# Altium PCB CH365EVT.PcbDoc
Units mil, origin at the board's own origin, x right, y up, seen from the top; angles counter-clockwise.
Board outline 3165 x 3014.02 mil, 2 copper layers (TopLayer, BottomLayer); 26 components, 99 nets, 425 pads, 157 vias.
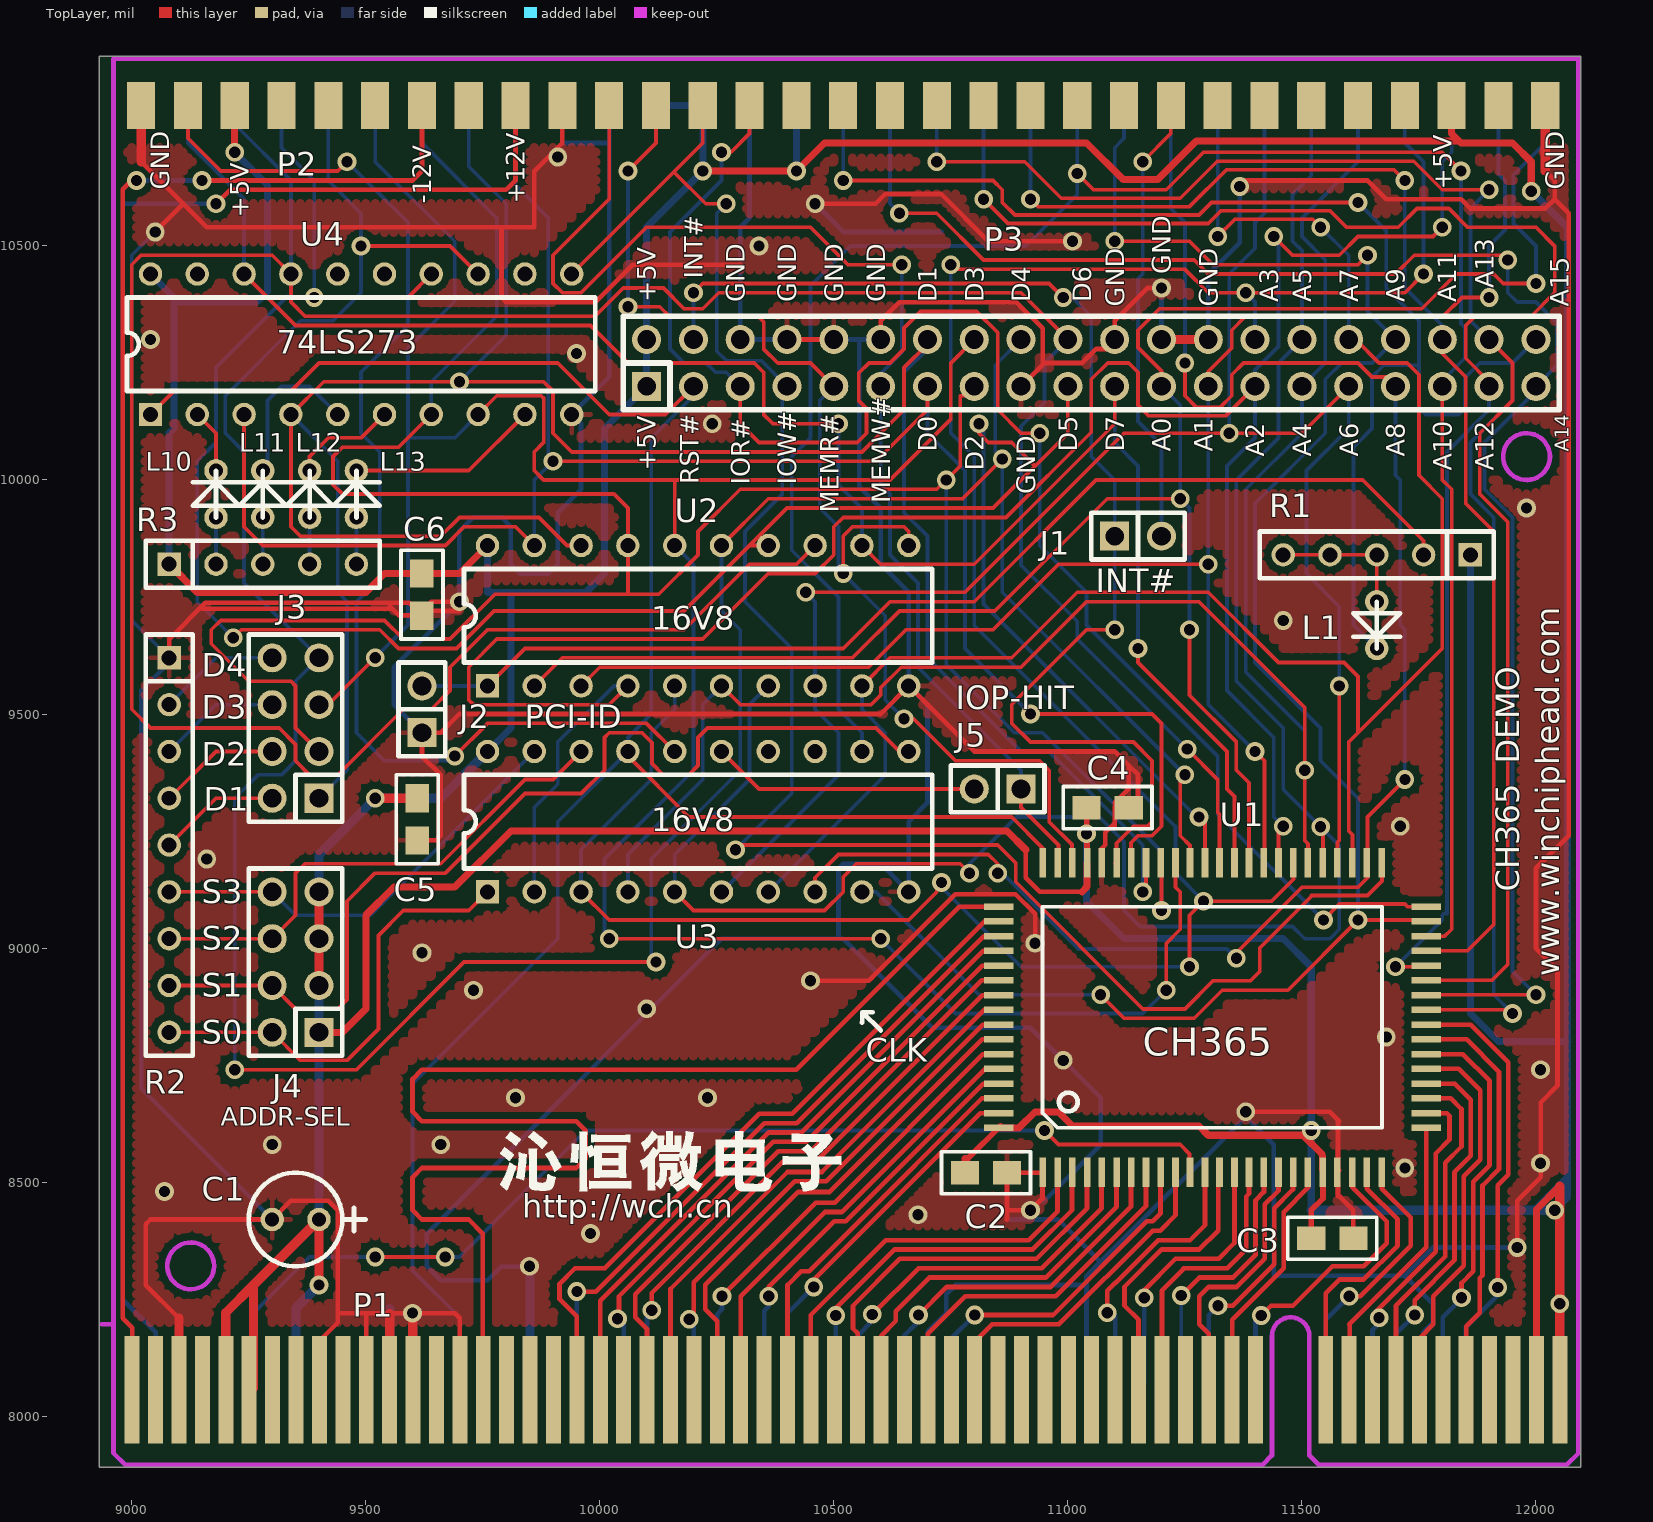
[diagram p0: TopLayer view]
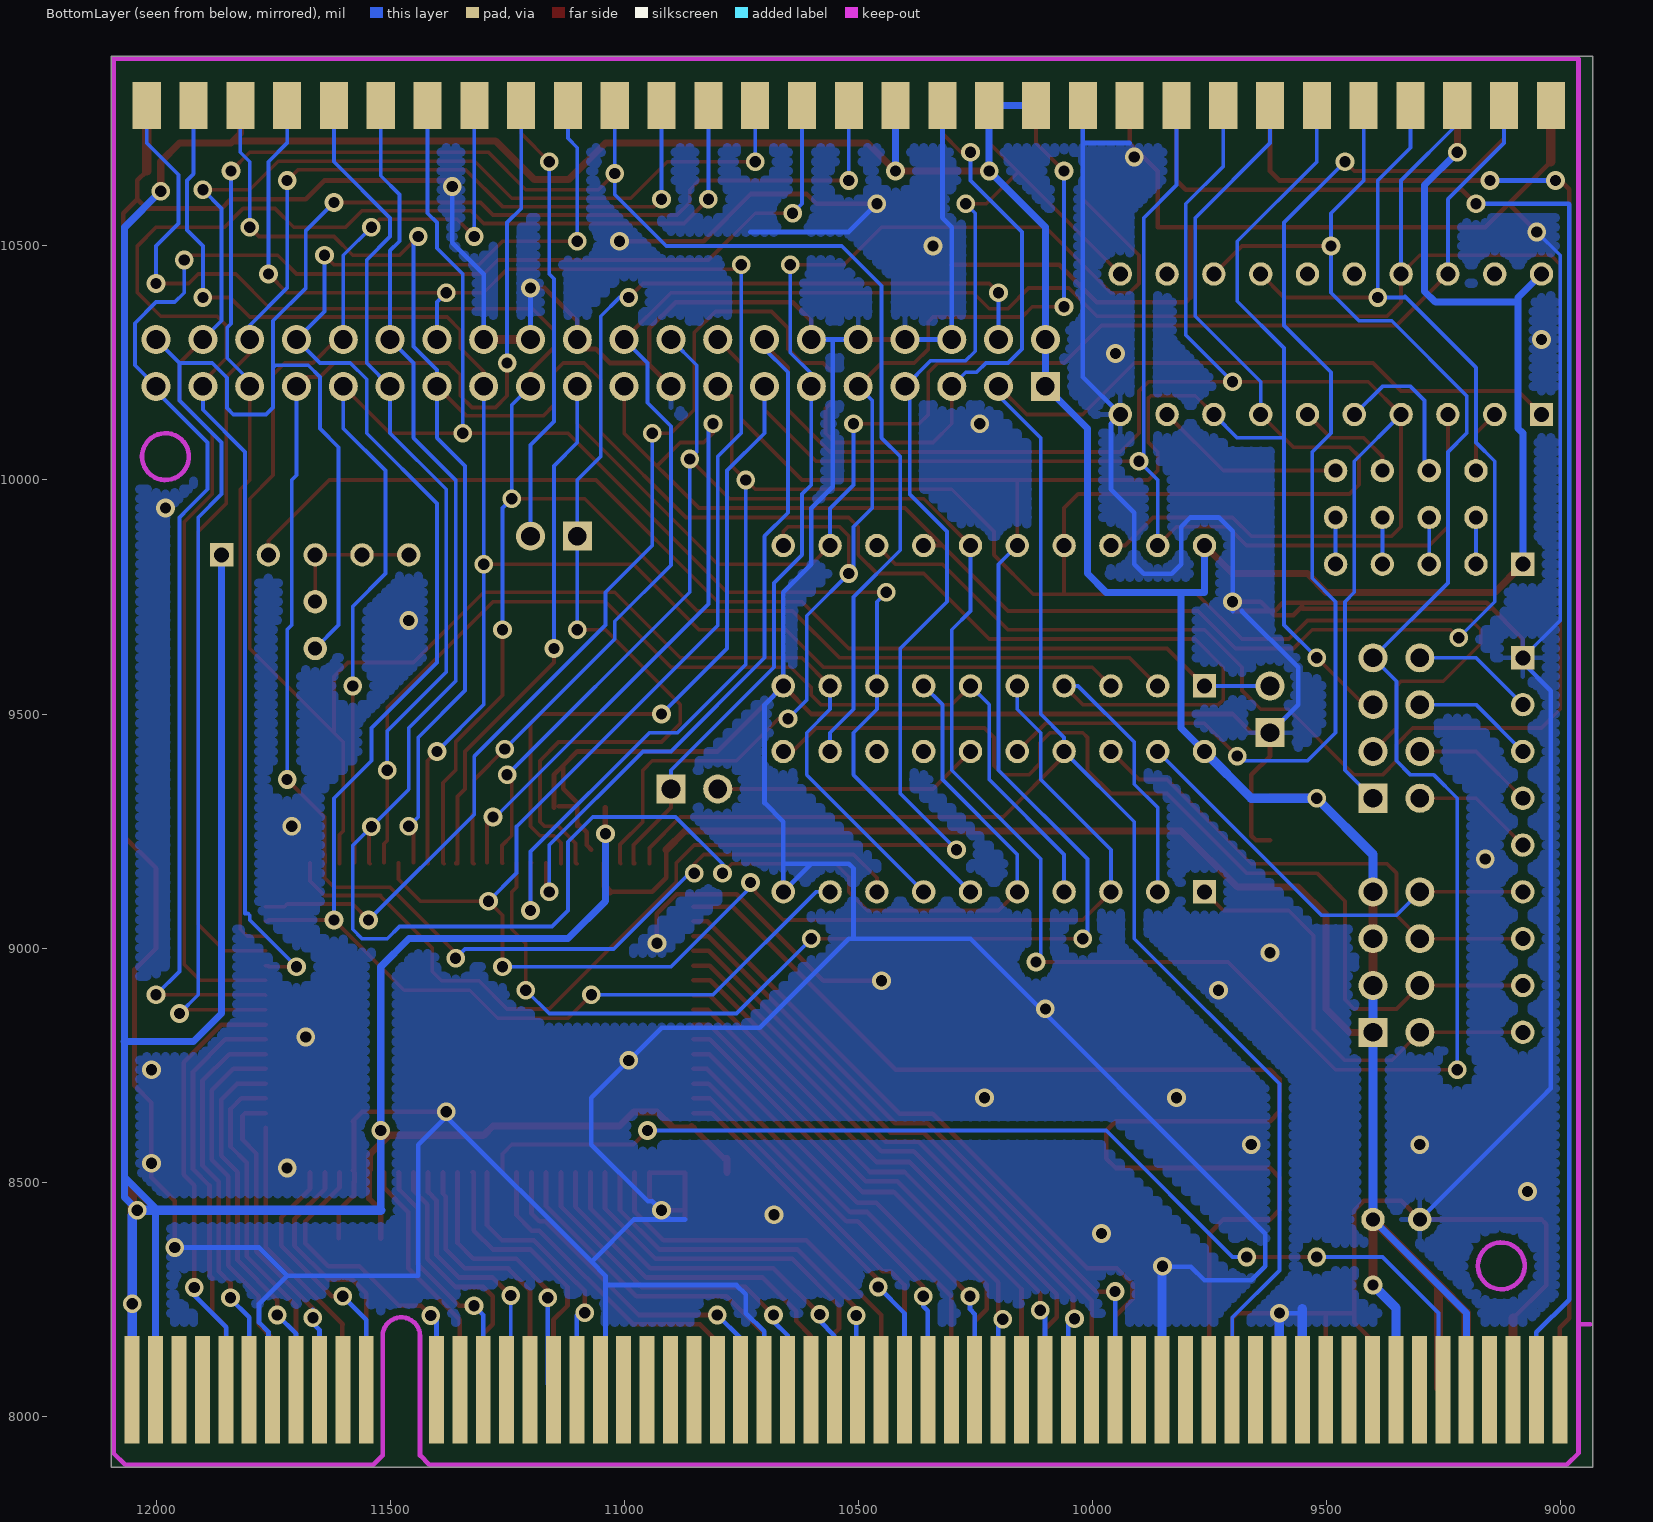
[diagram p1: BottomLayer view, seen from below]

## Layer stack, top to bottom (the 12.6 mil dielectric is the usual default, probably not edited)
TopSolder: solder mask 0.4, Solder Resist, Dk 3.5
TopLayer: signal copper 1.4
Dielectric1: core 12.6, FR-4, Dk 4.8
BottomLayer: signal copper 1.4
BottomSolder: solder mask 0.4, Solder Resist, Dk 3.5

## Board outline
8930.98,7890.98 12095.98,7890.98 12095.98,10905 8930.98,10905

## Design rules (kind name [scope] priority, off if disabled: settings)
Clearance Clearance_1 [(InPoly)] p1: gap=15 ignorepadtopadclearanceinfootprint=FALSE
Clearance [All] p2: gap=10 ignorepadtopadclearanceinfootprint=FALSE
FabricationTestPointUsage TestPointUsage [All] p1: valid=0 allowmultiple=FALSE
FabricationTestpoint Testpoint [All] p1: side=3 testpointundercomponent=TRUE minsize=40 maxsize=100 preferedsize=60 minholesize=20 maxholesize=40 preferedholesize=32 testpointgrid=1 allowsidetop=TRUE allowsidebottom=TRUE usegrid=TRUE gridtolerance=0.01
PasteMaskExpansion PasteMaskExpansion_1 [All] p1: expansion=0
PasteMaskExpansion [All] p2: expansion=0
PlaneClearance PlaneClearance_1 [All] p1: clearance=20
PlaneClearance [All] p2: clearance=10
PlaneConnect PlaneConnect_1 [All] p1: planeconnectstyle=Relief reliefexpansion=20 reliefentries=4 reliefconductorwidth=10 reliefairgap=10
PlaneConnect [All] p2: planeconnectstyle=Relief reliefexpansion=20 reliefentries=4 reliefconductorwidth=10 reliefairgap=10
PolygonConnect [All] p1: connectstyle=Relief reliefconductorwidth=10 reliefentries=4 polygonreliefangle="90 Angle" airgapwidth=10
RoutingPriority RoutingPriority_1 [InNet('+12')] p1: routingpriority=9
RoutingPriority RoutingPriority_2 [InNet('-12')] p2: routingpriority=8
RoutingPriority RoutingPriority_3 [InNet('VCC')] p3: routingpriority=5
RoutingPriority [All] p4: routingpriority=0
RoutingVias [All] p1: holewidth=24 width=40 viastyle="Through Hole" minholewidth=20 minwidth=30 maxholewidth=24 maxwidth=40
ShortCircuit ShortCircuit_1 [All] p1: allowed=FALSE
ShortCircuit [All] p2: allowed=FALSE
SolderMaskExpansion SolderMaskExpansion_1 [All] p1: expansion=8 istentingtop=FALSE
UnRoutedNet UnRoutedNet_1 [All] p1:
UnRoutedNet [All] p2:
Width Width_3 [InNet('VCC')] p1: maxlimit=20 minlimit=8 preferedwidth=15
Width Width_4 [InNet('GND')] p2: maxlimit=20 minlimit=8 preferedwidth=10
Width Width_1 [InNet('-12')] p3: maxlimit=20 minlimit=8 preferedwidth=10
Width Width_2 [InNet('+12')] p4: maxlimit=20 minlimit=8 preferedwidth=10
Width "Width Board" [All] p5: maxlimit=20 minlimit=8 preferedwidth=8
22 further rules are at their usual default settings.

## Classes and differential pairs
component class CH365EVT: C1 C2 C3 C4 C5 C6 J1 J2 J3 J4 J5 L1 P1 P2 R1 R2 U1 U2 U3
net class "Power Class": +12 -12 GND VCC

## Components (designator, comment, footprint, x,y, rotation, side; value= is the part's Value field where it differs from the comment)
C1 "100uF" CD0.1 9400,8420 r0 top
C2 "0.1uF" RC1 10780,8520 r0 top
C3 "0.1uF" RC1 11520,8380 r0 top
C4 "0.1uF" RC1 11040,9300 r0 top
C5 "0.1uF" RC1 9610,9320 r270 top
C6 "0.1uF" RC1 9620,9800 r270 top
J1 "" SIP2 11100,9880 r0 top
J2 "" SIP2 9620,9460 r90 top
J3 "4PIN" IDC8 9400,9320 r90 top
J4 "4PIN" IDC8 9400,8820 r90 top
J5 "" SIP2 10900,9340 r180 top
L1 "" DIODE0.1 11660,9740 r270 top
L10 "" DIODE0.1 9180,9920 r90 top
L11 "" DIODE0.1 9280,9920 r90 top
L12 "" DIODE0.1 9380,9920 r90 top
L13 "" DIODE0.1 9480,9920 r90 top
P1 "PCI" PCI32 9000.98,8045.98 r0 top
P2 "ISA" PC_BUS 8200,14400 r0 top
P3 "40PIN" IDC40 10100,10200 r0 top
R1 "4K7" SIP5 11860,9840 r180 top
R2 "4K7" SIP9 9080,9620 r270 top
R3 "4K7" SIP5 9080,9820 r0 top
U1 "CH365" PQFP80 11000.98,8670.98 r0 top
U2 "16V8" DIP20 9760,9560 r90 top
U3 "16V8" DIP20 9760,9120 r90 top
U4 "74LS273" DIP20 9040,10140 r90 top

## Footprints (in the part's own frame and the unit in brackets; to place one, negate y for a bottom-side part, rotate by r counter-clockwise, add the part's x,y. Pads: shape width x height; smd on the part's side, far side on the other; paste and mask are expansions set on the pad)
CD0.1 [mil]
  round 50 hole 30: 1(0,0) 2(-100,0)
  silkscreen extent -150,-100 100,100
DIODE0.1 [mil]
  round 50 hole 30: A(0,0) K(100,0)
  silkscreen extent 0,-50 100,50
DIP20 [mil]
  rect 50x50 hole 32: 1(0,0)
  round 50 hole 32: 2(0,-100) 3(0,-200) 4(0,-300) 5(0,-400) 6(0,-500) 7(0,-600) 8(0,-700) 9(0,-800) 10(0,-900) 11(300,-900) 12(300,-800) 13(300,-700) 14(300,-600) 15(300,-500) 16(300,-400) 17(300,-300) 18(300,-200) 19(300,-100) 20(300,0)
  silkscreen extent 50,-950 250,50
IDC8 [mil]
  rect 62x62 hole 40: 1(0,0)
  round 62 hole 40: 2(0,100) 3(100,0) 4(100,100) 5(200,0) 6(200,100) 7(300,0) 8(300,100)
  silkscreen extent -50,-50 350,150
IDC40 [mil]
  rect 62x62 hole 40: 1(0,0)
  round 62 hole 40: 2(0,100) 3(100,0) 4(100,100) 5(200,0) 6(200,100) 7(300,0) 8(300,100) 9(400,0) 10(400,100) 11(500,0) 12(500,100) 13(600,0) 14(600,100) 15(700,0) 16(700,100) 17(800,0) 18(800,100) 19(900,0) 20(900,100) 21(1000,0) 22(1000,100) 23(1100,0) 24(1100,100) 25(1200,0) 26(1200,100) 27(1300,0) 28(1300,100) 29(1400,0) 30(1400,100) 31(1500,0) 32(1500,100) 33(1600,0) 34(1600,100) 35(1700,0) 36(1700,100) 37(1800,0) 38(1800,100) 39(1900,0) 40(1900,100)
  silkscreen extent -50,-50 1950,150
PC_BUS [mil]
  rect 60x100 smd: 1(820,-3600) 2(920,-3600) 3(1020,-3600) 4(1120,-3600) 5(1220,-3600) 6(1320,-3600) 7(1420,-3600) 8(1520,-3600) 9(1620,-3600) 10(1720,-3600) 11(1820,-3600) 12(1920,-3600) 13(2020,-3600) 14(2120,-3600) 15(2220,-3600) 16(2320,-3600) 17(2420,-3600) 18(2520,-3600) 19(2620,-3600) 20(2720,-3600) 21(2820,-3600) 22(2920,-3600) 23(3020,-3600) 24(3120,-3600) 25(3220,-3600) 26(3320,-3600) 27(3420,-3600) 28(3520,-3600) 29(3620,-3600) 30(3720,-3600) 31(3820,-3600)
  rect 60x100 smd far side: 32(3820,-3600) 33(3720,-3600) 34(3620,-3600) 35(3520,-3600) 36(3420,-3600) 37(3320,-3600) 38(3220,-3600) 39(3120,-3600) 40(3020,-3600) 41(2920,-3600) 42(2820,-3600) 43(2720,-3600) 44(2620,-3600) 45(2520,-3600) 46(2420,-3600) 47(2320,-3600) 48(2220,-3600) 49(2120,-3600) 50(2020,-3600) 51(1920,-3600) 52(1820,-3600) 53(1720,-3600) 54(1620,-3600) 55(1520,-3600) 56(1420,-3600) 57(1320,-3600) 58(1220,-3600) 59(1120,-3600) 60(1020,-3600) 61(920,-3600) 62(820,-3600)
PCI32 [mil]
  rect 32x230 smd: 1(0,10) 2(50,10) 3(100,10) 4(150,10) 5(200,10) 6(250,10) 7(300,10) 8(350,10) 9(400,10) 10(450,10) 11(500,10) 12(550,10) 13(600,10) 14(650,10) 15(700,10) 16(750,10) 17(800,10) 18(850,10) 19(900,10) 20(950,10) 21(1000,10) 22(1050,10) 23(1100,10) 24(1150,10) 25(1200,10) 26(1250,10) 27(1300,10) 28(1350,10) 29(1400,10) 30(1450,10) 31(1500,10) 32(1550,10) 33(1600,10) 34(1650,10) 35(1700,10) 36(1750,10) 37(1800,10) 38(1850,10) 39(1900,10) 40(1950,10) 41(2000,10) 42(2050,10) 43(2100,10) 44(2150,10) 45(2200,10) 46(2250,10) 47(2300,10) 48(2350,10) 49(2400,10) 52(2550,10) 53(2600,10) 54(2650,10) 55(2700,10) 56(2750,10) 57(2800,10) 58(2850,10) 59(2900,10) 60(2950,10) 61(3000,10) 62(3050,10)
  rect 32x230 smd far side: 63(3050,10) 64(3000,10) 65(2950,10) 66(2900,10) 67(2850,10) 68(2800,10) 69(2750,10) 70(2700,10) 71(2650,10) 72(2600,10) 73(2550,10) 76(2400,10) 77(2350,10) 78(2300,10) 79(2250,10) 80(2200,10) 81(2150,10) 82(2100,10) 83(2050,10) 84(2000,10) 85(1950,10) 86(1900,10) 87(1850,10) 88(1800,10) 89(1750,10) 90(1700,10) 91(1650,10) 92(1600,10) 93(1550,10) 94(1500,10) 95(1450,10) 96(1400,10) 97(1350,10) 98(1300,10) 99(1250,10) 100(1200,10) 101(1150,10) 102(1100,10) 103(1050,10) 104(1000,10) 105(950,10) 106(900,10) 107(850,10) 108(800,10) 109(750,10) 110(700,10) 111(650,10) 112(600,10) 113(550,10) 114(500,10) 115(450,10) 116(400,10) 117(350,10) 118(300,10) 119(250,10) 120(200,10) 121(150,10) 122(100,10) 123(50,10) 124(0,10)
  KeepOutLayer lines w10: -65,150 -40,150 -40,-125 -15,-150 2415,-150 2435,-130 2435,125 cw(c2475,125) 2515,125 2515,-130 2535,-150 3065,-150 3090,-125 3090,150
PQFP80 [mil]
  rect 14x63 smd: 1(-55,-150) 2(-23,-150) 3(8,-150) 4(40,-150) 5(71,-150) 6(103,-150) 7(134,-150) 8(166,-150) 9(197,-150) 10(229,-150) 11(260,-150) 12(292,-150) 13(323,-150) 14(355,-150) 15(386,-150) 16(418,-150) 17(449,-150) 18(481,-150) 19(512,-150) 20(544,-150) 21(575,-150) 22(607,-150) 23(638,-150) 24(670,-150) 41(670,511) 42(638,511) 43(607,511) 44(575,511) 45(544,511) 46(512,511) 47(481,511) 48(449,511) 49(418,511) 50(386,511) 51(355,511) 52(323,511) 53(292,511) 54(260,511) 55(229,511) 56(197,511) 57(166,511) 58(134,511) 59(103,511) 60(71,511) 61(40,511) 62(8,511) 63(-23,511) 64(-55,511)
  rect 63x14 smd: 25(765,-55) 26(765,-24) 27(765,8) 28(765,39) 29(765,71) 30(765,102) 31(765,134) 32(765,165) 33(765,197) 34(765,228) 35(765,260) 36(765,291) 37(765,323) 38(765,354) 39(765,386) 40(765,417) 65(-149,417) 66(-149,386) 67(-149,354) 68(-149,323) 69(-149,291) 70(-149,260) 71(-149,228) 72(-149,197) 73(-149,165) 74(-149,134) 75(-149,102) 76(-149,71) 77(-149,39) 78(-149,8) 79(-149,-24) 80(-149,-55)
  silkscreen extent -55,-55 670,417
RC1 [mil]
  rect 60x50 smd: 1(0,0) 2(90,0)
  silkscreen extent -50,-45 140,45
SIP2 [mil]
  rect 62x62 hole 40: 1(0,0)
  round 62 hole 40: 2(100,0)
  silkscreen extent -50,-50 150,50
SIP5 [mil]
  rect 50x50 hole 32: 1(0,0)
  round 50 hole 32: 2(100,0) 3(200,0) 4(300,0) 5(400,0)
  silkscreen extent -50,-50 450,50
SIP9 [mil]
  rect 50x50 hole 32: 1(0,0)
  round 50 hole 32: 2(100,0) 3(200,0) 4(300,0) 5(400,0) 6(500,0) 7(600,0) 8(700,0) 9(800,0)
  silkscreen extent -50,-50 850,50

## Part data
C1: library part Pro70E3.TMP_100u_5
C2 C3 C4 C5 C6: library part Pro70E3.TMP_0.1u_4
J1 J5: library part Pro70E3.TMP_UnNamed_6
J2: library part Pro70E3.TMP_UnNamed_1
J3 J4: library part Pro70E3.TMP_4PIN_7
L1 L10 L11 L12 L13: library part Pro70E3.TMP_UnNamed_3
P1: library part Pro70E3.TMP_PCI_9
P2: library part Pro70E3.TMP_ISA_13
R1 R3: library part Pro70E3.TMP_4K7_2
R2: library part Pro70E3.TMP_4K7_11
U1: library part Pro70E3.TMP_CH361_8
U2: library part Pro70E3.TMP_16V8_12
U3: library part Pro70E3.TMP_16V8_10

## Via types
v1: diameter 40, hole 24, TopLayer to BottomLayer, 157 vias

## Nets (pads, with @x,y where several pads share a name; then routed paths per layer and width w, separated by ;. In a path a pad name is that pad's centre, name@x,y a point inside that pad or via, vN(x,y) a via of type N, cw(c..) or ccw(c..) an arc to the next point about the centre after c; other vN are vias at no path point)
+12: P1.123 P2.9 | length 3582.2
  TopLayer w10: v1(9180,10590) 9210,10620 9800,10620 9820,10640 P2.9
  BottomLayer w10: P1.123 9050.98,8179.02 8980.98,8249.02 8980.98,10589.02 8981.96,10590 v1(9180,10590)
-12: P1.1 P2.7 | length 3368.5
  TopLayer w10: P1.1 9000.98,8189.02 8980.98,8209.02 8980.98,10620.98 9000,10640 v1(9010,10640) ; v1(9150,10640) 9600,10640 9620,10660 P2.7
  BottomLayer w10: v1(9010,10640) v1(9150,10640)
A0: P2.32 P3.23 U1.50 U2.2 | length 4120.7
  TopLayer w8: U2.2 9920,9620 10540,9620 10640,9720 10844,9720 11084,9960 v1(11240,9960) ; P3.23 11200,10233 11150,10283 11150,10320 11196,10366 11756,10366 11830,10440 11910,10440 11930,10420 v1(12000,10420) ; v1(11260,9680) 11260,9540 11360,9440 11360,9380 11386.98,9353.02 U1.50 U1.50@11385,9180
  BottomLayer w8: P3.23 11240,10160 v1(11240,9960) 11260,9940 v1(11260,9680) ; v1(12000,10420) 12000,10500 11952,10548 11952,10652 12020,10720 P2.32
A1: P2.33 P3.25 U1.49 U2.3 | length 3680
  TopLayer w8: U2.3 10000,9600 10574,9600 10654,9680 10840,9680 10980,9820 v1(11300,9820) ; P3.25 11300,10232 11350,10282 11350,10320 11378,10348 11800,10348 11842,10390 v1(11900,10390) ; v1(11400,9420) 11420,9400 11420,9180 11418.98,9180 U1.49
  BottomLayer w8: P3.25 11300,9520 v1(11400,9420) ; v1@11900,10380 11900,10500 11934,10534 11934,10640 11920,10654 P2.33
A2: P2.34 P3.27 U1.48 U2.4 U3.2 | length 5246.9
  TopLayer w8: U2.4 10020,9520 9730,9520 9720,9530 9720,9600 9780,9660 10220,9660 10360,9800 10460,9800 10500,9840 10500,9900 10520,9920 10868,9920 11050,10102 11050,10215 11085,10250 11130,10250 11150,10230 11150,10160 11173,10137 11337,10137 P3.27 ; v1(11440,10520) 11480,10480 11580,10480 11620,10520 11780,10520 v1(11800,10540) ; U1.48 11449.98,9249.98 v1(11460,9260)
  BottomLayer w8: U3.2 9860,9300 9910,9350 9910,9440 10030,9560 U2.4 ; v1(11440,10520) 11450,10510 11450,10285 11400,10235 11400,10090 11340,10030 11340,9550 11440,9450 11440,9280 v1(11460,9260) ; v1(11800,10540) 11800,10680 11820,10700 P2.34
A3: P2.35 P3.28 U1.47 U2.5 U3.3 | length 5486.9
  TopLayer w8: U3.3 10020,9060 10660,9060 10720,9120 v1@10720,9140 ; v1(10750,10460) 10760,10450 11250,10450 11300,10400 11720,10400 v1(11760,10440) ; v1(11260,8960) 11260,9070 v1(11290,9100) 11435,9100 11481.98,9146.98 U1.47
  BottomLayer w8: U3.3 9960,9210 10110,9360 10110,9460 10160,9510 U2.5 ; v1@10720,9140 10900,8960 v1(11260,8960) ; v1(10750,10460) 10750,10100 10800,10050 10800,9689 11230,9259 ; 11230,9260 11230,9160 v1(11290,9100) ; v1(11380,10400) 11400,10380 P3.28 ; P2.35 11720,10720 11760,10680 v1(11760,10440)
  other v1: 10730,9140
A4: P2.36 P3.29 U1.46 U2.6 U3.4 | length 3927.5
  TopLayer w8: U2.6 10300,9520 10580,9520 10600,9540 10600,9556 10644,9600 10900,9600 11040,9740 11280,9740 11506,9514 11506,9230 11512.98,9223.02 U1.46
  BottomLayer w8: U3.4 10060,9200 10220,9360 10220,9520 U2.6 ; v1(11506,9380) 11506,9464 11380,9590 11380,9980 11500,10100 P3.29 11550,10250 11550,10470 11500,10520 11500,10560 11620,10680 P2.36
A5: P2.37 P3.30 U1.45 U2.7 U3.5 | length 4307.2
  TopLayer w8: U3.5 10200,9080 10480,9080 10520,9120 10520,9152 10548,9180 10770,9180 v1(10790,9160) ; v1(11540,9259) 11544.98,9254.02 U1.45 U1.45@11543,9180
  BottomLayer w8: U3.5 10160,9200 10320,9360 10320,9520 U2.7 ; v1(10790,9160) 10790,9180 10890,9280 11067,9280 11120,9227 11120,9080 11154,9046 11480,9046 11506,9020 11560,9020 11580,9040 11580,9219 11460,9339 11460,9470 11360,9570 11360,10000 11450,10090 11450,10250 P3.30 11500,10490 11480,10510 11480,10610 11520,10650 P2.37
A6: P2.38 P3.31 U1.44 U2.8 U3.6 | length 3931.8
  TopLayer w8: v1(10440,9760) 10780,9760 11120,10100 11500,10100 P3.31 ; U1.44 11575.98,9225.98 11580,9230 v1(11580,9560)
  BottomLayer w8: U3.6 10510,9370 10510,9460 10460,9510 10460,9740 v1(10440,9760) ; v1(11345,10100) 11345,10440 11400,10495 11400,10550 11420,10570 P2.38 ; v1(11580,9560) 11580,9730 11510,9800 11510,10020 11600,10110 P3.31
A7: P2.39 P3.32 U1.43 U2.9 U3.7 | length 4021.8
  TopLayer w8: U2.9 10620,9620 10880,9620 11020,9760 11300,9760 11450,9610 11590,9610 11620,9580 11620,9460 ; v1(11320,10520) 11357,10557 11523,10557 v1(11540,10540) ; P3.32 11615,10300 11665,10250 11725,10250 11750,10225 11750,10010 11800,9960 11800,9640 11600,9440 11600,9250 11607.98,9242.02 U1.43@11607.98,9180
  BottomLayer w8: U3.7 10610,9370 10610,9460 10560,9510 U2.9 ; v1(11320,10520) P2.39 ; v1(11540,10540) 11600,10480 P3.32
A8: P2.40 P3.33 U1.42 U3.8 | length 3712.3
  TopLayer w8: U3.8 10460,9150 10510,9200 10830,9200 10850,9180 v1(10850,9160) ; v1(11250,10250) 11250,10180 11275,10155 11325,10155 11350,10180 11350,10225 11375,10250 11620,10250 11650,10220 11680,10220 P3.33 ; v1(11360,8978) 11360,8990 11500,9130 11620,9130 11640,9150 11640,9181.98 U1.42@11640,9200 ; U1.42 11638.98,9200 U1.42@11640,9200 ; v1(11720,9360) 11640,9280 U1.42@11640,9200
  BottomLayer w8: v1@10840,9160 10860,9160 11022,8998 11340,8998 v1(11360,8978) ; P2.40 11220,10580 11250,10550 v1(11250,10250) ; P3.33 11700,10010 11710,10000 11710,9690 11720,9680 v1(11720,9360)
A9: P2.41 P3.34 U1.39 U3.9 | length 3973.4
  TopLayer w8: v1(11070,8900) 11120,8850 11270,8850 11330,8910 11470,8910 v1(11620,9060) 11760,9060 11760,9056.98 U1.39 ; v1(11100,10510) 11260,10510 11310,10460 11620,10460 v1(11640,10480)
  BottomLayer w8: U3.9 10590,9120 10810,8900 v1(11070,8900) ; v1(11100,10510) 11100,10710 11120,10730 P2.41 ; v1(11620,9060) 11620,9320 11540,9400 11540,9470 11400,9610 11400,9950 11550,10100 11550,10215 11585,10250 11650,10250 P3.34 11640,10360 v1(11640,10480)
A10: P2.42 P3.35 U1.38 U3.12 | length 4510.4
  TopLayer w8: v1(11020,10655) 11055,10620 11210,10620 11290,10700 11800,10700 v1(11840,10660) ; U1.38 11804.98,9024.98 11820,9040 11820,9980 11800,10000 P3.35
  BottomLayer w8: U3.12 10560,9460 10510,9510 10510,9750 10410,9850 10410,10050 10450,10090 10450,10415 10535,10500 10910,10500 11020,10610 P2.42 ; P3.35 11800,10212 11848,10260 11848,10326 11840,10334 v1(11840,10660)
A11: P2.43 P3.36 U1.37 | length 2884.8
  TopLayer w8: v1(10920,10600) 10936,10584 11260,10584 11339,10663 11697,10663 v1(11720,10640) ; U1.37 11853.98,8993.98 11910,9050 11910,9890 11850,9950 11850,10220 11800,10270 P3.36
  BottomLayer w8: v1(10920,10600) P2.43 ; v1(11720,10640) 11720,10410 11800,10330 P3.36
A12: P2.44 P3.37 U1.36 | length 3381
  TopLayer w8: v1(10820,10600) 10872,10548 11300,10548 11327,10575 11560,10575 11595,10540 11706,10540 11746,10580 11814,10580 11854,10540 12000,10540 12040,10500 12040,10400 11990,10350 11870,10350 11850,10330 11850,10260 11900,10210 P3.37 ; v1(11700,8960) 11760,8960 11760,8961.98 U1.36
  BottomLayer w8: v1(10820,10600) P2.44 ; v1(11700,8960) 11800,9060 11800,9070 11803.92,9073.92 11810,9073.92 11810,10060 11900,10150 P3.37
A13: P2.45 P3.38 U1.35 | length 3341.1
  TopLayer w8: v1(10720,10680) 10908,10680 10986,10602 11240,10602 11319,10681 11739,10681 11800,10620 v1(11900,10620) ; U1.35 11905.98,8930.98 11940,8965 11940,9910 11880,9970 11880,10100 11950,10170 11950,10250 P3.38
  BottomLayer w8: v1(10720,10680) P2.45 ; P3.38 11860,10340 11860,10580 v1(11900,10620)
A14: P2.46 P3.39 U1.34 | length 3594
  TopLayer w8: v1(10640,10570) 10720,10570 10820,10470 11270,10470 11300,10440 11700,10440 11740,10480 11930,10480 v1(11940,10470) ; U1.34 11767,8900 v1(12000,8900)
  BottomLayer w8: P2.46 10620,10590 v1(10640,10570) ; v1(11940,10470) 11940,10400 11960,10380 12000,10380 12045,10335 12045,10245 P3.39 12000,10190 11890,10080 11890,9980 11930,9940 11950,9920 11950,8950 v1(12000,8900)
A15: L1.K P2.47 P3.40 U1.33 | length 4551.7
  TopLayer w8: v1(10520,10640) 10840,10640 10860,10620 10860,10593 10887,10566 11280,10566 11307,10593 v1(11620,10593) ; U1.33 11942.02,8867.98 v1(11950,8860)
  BottomLayer w8: v1(10520,10640) P2.47 ; v1(11620,10593) 11680,10533 11680,10410 11750,10340 11750,10155 11765,10140 11835,10140 11848.62,10153.62 11848.62,10218.62 11880,10250 11950,10250 ; L1.K 11610,9690 11610,10070 11650,10110 11650,10220 11675,10245 11745,10245 11750,10240 ; v1(11950,8860) 11910,8900 11910,9920 11860,9970 11860,10080 11950,10170 11950,10250 ; P3.40 11950,10250
AD0: P1.67 U1.32 | length 946.2
  TopLayer w10: U1.32 11860.98,8835.98 11940.98,8755.98 11940.98,8515.98 11918.23,8493.23 v1(11918.23,8274.77)
  BottomLayer w10: P1.67 11850,8056.96 11850,8190 11918.23,8258.23 v1(11918.23,8274.77)
AD1: P1.58 U1.31 | length 892.6
  TopLayer w10: U1.31 11851.98,8804.98 11920.98,8735.98 11920.98,8527.7 11885.98,8492.7 11885.98,8300.98 11880,8295 11880,8221 11850.98,8191.98 P1.58
AD2: P1.68 U1.30 | length 860
  TopLayer w10: U1.30 11843.98,8772.98 11900.98,8715.98 11900.98,8535.98 11865.98,8500.98 11865.98,8309.27 11841,8284.28 v1(11841,8253)
  BottomLayer w10: P1.68 11800.98,8210.98 11841,8251 v1(11841,8253)
AD3: P1.56 U1.29 | length 828.4
  TopLayer w10: P1.56 11750.38,8056.58 11750.38,8165.38 11780.98,8195.98 11780.98,8255.98 11845.98,8320.98 11845.98,8512.7 11880.98,8547.7 11880.98,8695.98 11834.98,8741.98 U1.29
AD4: P1.70 U1.28 | length 805.4
  TopLayer w10: v1(11740.98,8215.98) 11740.98,8247.7 11825.98,8332.7 11825.98,8520.98 11860.98,8555.98 11860.98,8675.98 11826.98,8709.98 U1.28
  BottomLayer w10: P1.70@11700.98,8045.98 11700.98,8175.98 v1(11740.98,8215.98)
AD5: P1.55 U1.27 | length 752.5
  TopLayer w10: P1.55@11700.98,8045.98 11700.98,8235.98 11805.98,8340.98 11805.98,8540.98 11840.98,8575.98 11840.98,8655.98 11817.98,8678.98 U1.27
AD6: P1.71 U1.26 | length 727.9
  TopLayer w10: v1(11665,8210) 11660.98,8210 11660.98,8225.98 11785.98,8350.98 11785.98,8560.98 11815.24,8590.24 11815.24,8641.72 11809.98,8646.98 U1.26
  BottomLayer w10: P1.71 11650.98,8184.58 11665,8198.6 v1@11665,8227
AD7: P1.53 U1.25 | length 630.4
  TopLayer w10: P1.53 11602,8055.98 11602,8195 11600.98,8195 11600.98,8195.98 11765.98,8360.98 U1.25
AD8: P1.52 U1.23 | length 585.6
  TopLayer w10: P1.52 11550.98,8261.98 11581,8292 11632.17,8292 11704.34,8364.17 11704.34,8420.62 11638.98,8485.98 U1.23
AD9: P1.76 U1.22 | length 685
  TopLayer w10: v1(11413,8215) 11433.98,8235.98 11480.98,8235.98 11565.41,8320.41 11632.3,8320.41 11680.98,8369.1 11680.98,8415.7 11607.98,8488.7 U1.22
  BottomLayer w10: P1.76 11400.98,8204.98 11413,8204.98 v1(11413,8215)
AD10: P1.48 U1.19 | length 542.1
  TopLayer w10: P1.48@11350.98,8045.98 P1.48 11350.98,8205.98 11460.98,8315.98 11460.98,8435.98 11512.98,8487.98 U1.19
AD11: P1.78 U1.18 | length 570.6
  TopLayer w10: v1(11320.98,8235.98) 11352.7,8235.98 11440.98,8324.27 11440.98,8444.27 11480.98,8484.27 U1.18@11480.98,8515.98 ; U1.18@11481.98,8516.98 U1.18@11480.98,8515.98 ; U1.18 11480.98,8520.98 U1.18@11480.98,8515.98
  BottomLayer w10: P1.78@11300.98,8045.98 11300.98,8215.98 v1(11320.98,8235.98)
AD12: P1.47 U1.17 | length 578.4
  TopLayer w10: P1.47 11300.98,8175.98 11280.98,8195.98 11280.98,8255.98 11300.98,8275.98 11360.98,8275.98 11420.98,8335.98 11420.98,8452.55 11449.98,8481.55 U1.17
AD13: P1.79 U1.16 | length 590.7
  TopLayer w10: v1@11240.98,8255.98 11280.98,8295.98 11352.7,8295.98 11400.98,8344.27 11400.98,8460.83 11418.98,8478.83 U1.16
  BottomLayer w8: v1(11242.44,8257.44) 11242.44,8055.98 P1.79
AD14: P1.45 U1.15 | length 607.1
  TopLayer w10: P1.45@11200.98,8045.98 11200.98,8268 11247,8314.02 11247,8315.98 11340.98,8315.98 11380.98,8355.98 11380.98,8469.12 11386.98,8475.12 U1.15
AD15: P1.81 U1.14 | length 603.8
  TopLayer w10: v1(11163,8253) 11163,8269 11229.98,8335.98 11321.98,8335.98 11355.98,8369.98 U1.14
  BottomLayer w10: P1.81 11163,8068 v1(11163,8253)
AD16: P1.93 U1.5 | length 834.9
  TopLayer w10: v1(10582.3,8217.3) 10680.98,8315.98 10943.98,8315.98 11071.98,8443.98 U1.5
  BottomLayer w10: P1.93 10550.98,8171.98 10582.3,8203.3 v1(10582.3,8217.3)
AD17: P1.32 U1.4 | length 847.3
  TopLayer w10: P1.32 10550.98,8177.02 10540.98,8187.02 10540.98,8235.98 10640.98,8335.98 10932.98,8335.98 11040.98,8443.98 U1.4
AD18: P1.94 U1.3 | length 848
  TopLayer w10: v1(10504,8215) 10504,8229.98 10630,8355.98 10924.7,8355.98 11008.98,8440.27 U1.3
  BottomLayer w10: P1.94 10504,8059 v1(10504,8215)
AD19: P1.30 U1.2 | length 862.2
  TopLayer w10: P1.30 10450.98,8215.98 10610.98,8375.98 10916.41,8375.98 10977.98,8437.55 U1.2
AD20: P1.96 U1.79 | length 800.7
  TopLayer w10: v1(10456.98,8275.98) 10456.98,8291.09 10812.87,8646.98 U1.79
  BottomLayer w10: P1.96 10400.98,8219.98 v1(10456.98,8275.98)
AD21: P1.29 U1.78 | length 840.3
  TopLayer w10: P1.29 10400.98,8279.98 10430.58,8309.58 10447.18,8309.58 10533.58,8395.98 10816.58,8678.98 U1.78
AD22: P1.97 U1.77 | length 894.9
  TopLayer w10: v1(10360.98,8255.98) 10360.98,8275.98 10500.98,8415.98 10525.3,8415.98 10819.3,8709.98 U1.77
  BottomLayer w10: P1.97 10350.98,8224.98 10360.98,8234.98 v1(10360.98,8255.98)
AD23: P1.27 U1.76 | length 962.3
  TopLayer w10: P1.27@10300.98,8045.98 10300.98,8255.98 10480.98,8435.98 10517.01,8435.98 10823.01,8741.98 U1.76
AD24: P1.100 U1.73 | length 1122.9
  TopLayer w10: v1(10191,8207) 10200.98,8216.98 10200.98,8285.98 10416.53,8501.53 10483.53,8501.53 10817.98,8835.98 U1.73
  BottomLayer w10: v1(10191,8207) 10191,8198.02 10200.98,8198.02 P1.100
AD25: P1.24 U1.72 | length 1173.6
  TopLayer w10: P1.24@10150.98,8045.98 10150.98,8271.53 10400.98,8521.53 10474.53,8521.53 10820.98,8867.98 U1.72
AD26: P1.102 U1.71 | length 1215.6
  TopLayer w10: v1(10110.98,8225.98) 10110.98,8263.02 10390.98,8543.02 10460.98,8543.02 10816.94,8898.98 U1.71
  BottomLayer w10: P1.102 10100.98,8215.98 v1(10110.98,8225.98)
AD27: P1.23 U1.70 | length 1269.2
  TopLayer w10: P1.23 10100.98,8185.98 10075.56,8211.4 10075.56,8260.56 10380.98,8565.98 10450.98,8565.98 10815.98,8930.98 U1.70
AD28: P1.103 U1.69 | length 1310
  TopLayer w10: v1(10038,8208) 10040.98,8210.98 10040.98,8255.98 10370.98,8585.98 10440.98,8585.98 10816.98,8961.98 U1.69
  BottomLayer w10: v1(10038,8208) 10050.98,8195.02 P1.103
AD29: P1.21 U1.68 | length 1350.8
  TopLayer w10: P1.21 10000.98,8245.98 10360.98,8605.98 10430.98,8605.98 10818.98,8993.98 U1.68
AD30: P1.105 U1.67 | length 1425.4
  TopLayer w10: v1(9950.98,8265.98) 9990.98,8265.98 10350.98,8625.98 10420.98,8625.98 10819.98,9024.98 U1.67
  BottomLayer w10: P1.105 v1(9950.98,8265.98)
AD31: P1.20 U1.66 | length 1500.9
  TopLayer w10: P1.20 9950.98,8213.02 9914,8250 9914,8283 9946.98,8315.98 10010.98,8315.98 10340.98,8645.98 10410.98,8645.98 10821.98,9056.98 U1.66
CBE0: P1.73 U1.24 | length 579.6
  TopLayer w10: v1(11600.98,8255.98) 11624.43,8255.98 11732.71,8364.25 11732.71,8424.25 11670.98,8485.98 U1.24
  BottomLayer w10: P1.73 11550.98,8205.98 v1(11600.98,8255.98)
CBE1: P1.44 U1.13 | length 610.1
  TopLayer w10: P1.44 11150.98,8205.98 11120.98,8235.98 11120.98,8275.98 11200.98,8355.98 11280.98,8355.98 11320.98,8395.98 11320.98,8520.98 U1.13
CBE2: P1.33 U1.6 | length 819.2
  TopLayer w10: P1.33 10600.98,8171.98 10632.14,8203.14 10632.14,8224.14 10703.98,8295.98 10952.98,8295.98 11103.98,8446.98 U1.6
CBE3: P1.26 U1.74 | length 1078.9
  TopLayer w10: P1.26 10250.98,8203.02 10225.39,8228.61 10225.39,8280.39 10423.85,8478.85 10490.98,8478.85 10817.11,8804.98 U1.74
CLK: P1.16 U1.65 | length 2881.3
  TopLayer w10: P1.16@9750,8056.96 9750,8390 9720,8420 9620,8420 9600,8440 9600,8510 9620,8530 9950,8530 9970,8550 9970,8610 9950,8630 9620,8630 9600,8650 9600,8720 9620,8740 10420,8740 10767.98,9087.98 U1.65
D0: P2.54 P3.13 U1.58 U2.19 U4.3 | length 4218.9
  TopLayer w8: U4.3 9240,9900 9280,9860 9670,9860 9710,9900 9820,9900 U2.19 ; v1(9900,10040) 10590,10040 10700,10150 P3.13 ; v1(10920,9500) 11180,9500 11200,9480 11200,9260 11180,9240 11150,9240 11134.98,9224.98 U1.58@11134.98,9180
  BottomLayer w8: P2.54 9820,10630 9890,10560 9890,10050 v1(9900,10040) 9860,10000 U2.19 ; P3.13 10700,10100 10780,10020 10780,9640 v1(10920,9500)
D1: J3.1 P2.55 P3.14 U1.57 U2.18 U4.4 | length 5642.6
  TopLayer w8: U2.18 9930,9860 9870,9920 9700,9920 9660,9880 9360,9880 9340,9900 U4.4 9410,10210 9880,10210 9900,10190 9900,10100 9940,10060 10560,10060 10650,10150 10650,10240 10700,10290 P3.14 ; v1(11160,9120) 11166.98,9126.98 U1.57
  BottomLayer w8: U4.4 9440,10040 9440,9760 9460,9740 9460,9380 J3.1 ; v1(9700,10210) 9800,10310 9800,10590 9720,10670 P2.55 ; P3.14 10700,10280 10650,10230 10650,9930 10700,9880 10700,9620 10900,9420 10960,9420 11160,9220 v1(11160,9120)
D2: J3.3 P2.56 P3.15 U1.56 U2.17 U4.7 | length 5594.2
  TopLayer w8: J3.3 9350,9470 9350,9560 9340,9570 9250,9570 9170,9650 9170,9680 9190,9700 9540,9700 9580,9660 9680,9660 9776,9756 10126,9756 10210,9840 10210,9890 10300,9980 10720,9980 10770,10030 10770,10180 10800,10180 P3.15 ; U4.7 9570,10070 9450,10070 9430,10050 9430,9990 9450,9970 10030,9970 10060,9940 10060,9756 ; U1.56 11200,9184 v1(11200,9080)
  BottomLayer w8: P2.56 9620,10720 9780,10560 9780,10350 9640,10210 U4.7 ; v1(10740,10000) 10740,9606 10886,9460 10946,9460 11200,9206 v1(11200,9080)
D3: J3.5 P2.57 P3.16 U1.55 U2.16 U4.8 | length 5762.7
  TopLayer w8: J3.5 9420,9520 v1(9520,9620) ; U4.8 9780,10180 9875,10180 9880,10175 9880,10080 9860,10060 9860,10020 9880,10000 10620,10000 10750,10130 10750,10250 P3.16 ; v1(10020,9020) v1(10600,9020) ; U2.16 10160,10000 ; v1(11210,8910) 11210,9010 11240,9040 11240,9120 11229.98,9130.02 U1.55
  BottomLayer w8: v1(9520,9620) 9590,9690 9590,10282 9690,10382 9690,10510 9520,10680 P2.57 ; 9590,10090 9690,10090 U4.8 ; v1(10020,9020) 10010,9030 10010,9190 10200,9380 10200,9820 U2.16 ; v1(10600,9020) 10760,8860 11160,8860 v1(11210,8910)
D4: J3.7 P2.58 P3.18 U1.54 U2.15 U4.13 | length 6709.9
  TopLayer w8: v1(9220,8740) 9480,8740 9710,8970 v1(10120,8970) ; v1(9490,10500) 9680,10500 U4.13 ; U2.15 10360,9960 10775,9960 v1(10860,10045) ; v1(11250,9370) 11240,9360 11240,9240 11260.98,9219.02 U1.54 U1.54@11260,9181
  BottomLayer w8: v1(9220,8740) 9220,9320 9270,9370 9320,9370 9350,9400 9350,9570 J3.7 9240,9780 9240,10060 9200,10100 9200,10180 9360,10340 9430,10340 9490,10400 9490,10570 9420,10640 P2.58 ; v1(10120,8970) 10110,8980 10110,9190 10300,9380 10300,9680 10260,9720 U2.15 ; P3.18 10845,10245 10845,10060 v1(10860,10045) 10860,9760 v1@11260,9360
D5: P2.59 P3.19 U1.53 U2.14 U4.14 | length 5054.6
  TopLayer w8: v1(9217,9663) 9234,9680 9530,9680 9570,9640 9694,9640 9774,9720 10180,9720 10400,9940 10840,9940 11000,10100 P3.19 ; v1(9390,10390) 9590,10390 U4.14 ; 10320,9860 U2.14 ; v1(10810,10120) 10810,10100 10830,10080 10880,10080 10930,10030 ; v1(11280,9280) 11292.98,9267.02 U1.53
  BottomLayer w8: v1(9217,9663) 9140,9740 9140,10040 9180,10080 9180,10240 9331.93,10391.93 9333.86,10390 v1(9390,10390) 9390,10640 9320,10710 P2.59 ; v1(10810,10120) 10820,10110 10820,9735 v1@11277.5,9277.5
D6: P2.60 P3.20 U1.52 U2.13 U4.17 | length 6666.2
  TopLayer w8: U2.13 10420,9820 10320,9820 10180,9680 9760,9680 9680,9600 9680,9550 9640,9510 9580,9510 9440,9370 9380,9370 9350,9400 9350,9435 9315,9470 9040,9470 9000,9510 9000,10460 9020,10480 9300,10480 U4.17 9340,10380 9370,10350 9990,10350 10050,10410 10136,10410 10180,10366 10220,10366 10254,10400 10900,10400 P3.20 ; v1(11255,9425) 11320,9360 11320,9290 11323.98,9286.02 U1.52 11322,9180 U1.52@11320,9180
  BottomLayer w8: P2.60 9220,10760 9340,10640 U4.17 ; P3.20 10950,10250 10950,10165 10900,10115 10900,9818 11020,9698 11020,9660 v1(11255,9425)
D7: P2.61 P3.21 U1.51 U2.12 U4.18 | length 4044.5
  TopLayer w8: U4.18 9350,10330 9980,10330 10060,10250 10330,10250 10350,10230 10350,10140 10370,10120 v1@10516,10120 ; U2.12 10600,9820 10800,9820 11100,10120 P3.21 ; v1(11150,9640) 11150,9610 11340,9420 11340,9340 11355.98,9324.02 11355.98,9180 11360,9180 U1.51@11360,9181.98
  BottomLayer w8: P2.61 9120,10720 9240,10600 U4.18 ; v1(10510,10120) 10510,9989 10560,9939 U2.12 ; P3.21 11100,10080 11150,10030 v1(11150,9640)
DEVSEL: P1.37 U1.10 | length 735.8
  TopLayer w10: P1.37 10800.98,8158.98 10837.98,8195.98 10980.98,8195.98 11180.98,8395.98 11196.98,8395.98 11229.98,8428.98 U1.10
FRAME: P1.91 U1.7 | length 795.5
  TopLayer w10: v1(10680.98,8215.98) 10740.98,8275.98 10962.98,8275.98 11134.98,8447.98 U1.7
  BottomLayer w10: P1.91 10650.98,8172.98 10680.98,8202.98 v1(10680.98,8215.98)
GND: C1.2 C2.2 C3.2 C4.2 C5.2 C6.2 J2.1 P1.3 P1.9 P1.11 P1.12 P1.13 P1.15 P1.69 P1.83 P1.90 P1.107 P1.112 P1.113 P2.1 P2.10 P2.31 P2.49 P2.52 P3.6 P3.8 P3.10 P3.12 P3.17 P3.22 P3.24 P3.26 R2.1 U1.1 U1.21 U1.60 U2.10 U3.10 U4.10 | length 27372.6
  TopLayer w10: 9020,10680 9160,10540 9860,10540 9860,10660 9920,10720 P2.10 ; v1(9050,10530) 9109.91,10589.91 9109.91,10590.09 ; R2.1 9080,9660 9157.5,9737.5 9592.5,9737.5 9610,9720 9700,9720 ; 9100.98,8209.02 9030,8280 9030,8410 9040,8420 C1.2 9340,8460 9420,8460 9440,8440 9440,8200 9400,8160 P1.9@9400,8060 ; 9150,9725 9551,9725 ; 9440,8220 v1(9600,8220) 9690,8220 9700.98,8209.02 P1.15 ; 9500,8220 9500.98,8219.02 P1.11 ; 9550,8220 9550.98,8219.02 ; 9551,9730 9569.99,9711.01 9611.01,9711.01 9640,9740 v1(9700,9740) ; P1.13@9600,8100 9600.98,8100 P1.13 ; C5.2@9620,9230 9650,9230 9660,9240 9660,9370 9620,9410 J2.1 9660,9460 9700,9500 10600,9500 U2.10 10800,9420 11100,9420 11130,9390 ; 9790,10540 9790,10390 9800,10380 9990,10380 10070,10460 10300,10460 ; P3.8 P3.10 ; v1(10450,8930) 10574.64,8930 10759.63,9114.98 10888.15,9114.98 10930,9073.13 v1(10930,9010) ; v1(10460,10590) 10589,10590 10610,10611 10729,10611 10830,10510 v1(11010,10510) ; P3.12 10600,10340 10640,10380 10890,10380 10946,10324 10946,10250 ; 10870,8420 C2.2 10945,8520 U1.1 10945.98,8464.98 10944.98,8464.98 v1(10920,8440) 10870,8440 ; P3.17 10946,10246 10946,10250 ; U1.60@11070,9210 11078.02,9218.02 ; 11080,9220 11080,9247 11100,9267 ; 11100,9260 11100,9303 C4.2@11140,9303 ; C4.2@11100,9310 11110,9320 11130,9340 11130,9390 ; C4.2@11150,9300 11150,9370 11130,9390 ; v1(11200,10410) 11170,10410 11100,10340 P3.22 11100,10280 11061,10280 11031,10250 10946,10250 ; v1(11367,10627) 11380,10640 11640,10640 11680,10600 11840,10600 11860,10580 12020,10580 12040,10600 ; v1(11380,8650) 11560,8650 11580,8630 ; U1.21@11575.98,8500 U1.21 U1.21@11580,8525 ; U1.21@11577,8500 11577,8470 11581.02,8470 ; U1.21@11577,8525 11577,8630 ; 11580,8470 11610,8440 C3.2 ; v1(11960,8360) 11960,8460 12010,8510 12010,8670 12045.98,8705.98 12045.98,8954.02 12000,9000 12000,9170 12070,9240 12070,10570 12040,10600 ; 12020,10660 12040,10640 12040,10600
  TopLayer w20: 9020,10680 P2.1 ; P1.3 9100.98,8209.02 ; P1.12 9550.98,8219.02 ; P1.13@9600,8100 v1(9600,8220) ; P3.24 P3.26 ; 12020,10660 P2.31
  BottomLayer w8: v1(9050,10530) 9000,10480 9000,9700 9000.98,9699.02 R2.1
  BottomLayer w10: R2.1 9080,9610 9020,9550 9020,8700 9040,8680 C1.2 ; 9550.98,8229.02 9560,8220 v1(9600,8220) ; J2.1 9560,9520 9560,9600 9680,9720 ; 9700,9720 9700,9890 9730,9920 9790,9920 9810,9900 9810,9820 9830,9800 9890,9800 9910,9820 9910,9930 9960,9980 9960,10120 U4.10 10020,10220 10020,10720 ; v1(9850,8320) 9850.98,8319.02 9789.02,8319.02 9760,8290 9660,8290 9630,8320 9630,8390 10260,9020 10520,9020 10710,8830 10920,8830 11070,8680 11070,8580 10949,8459 10940,8459 10901,8420 ; 9920,10720 10020,10720 ; P2.52 10020,10720 ; P2.49 10320,10560 10300,10540 P3.6 P3.8 ; v1(10460,10590) 10520,10530 10730,10530 ; P3.10 10554,10300 ; 10510,9020 10510,9170 10520,9180 10660,9180 ; 10600,9180 U3.10 10660,9160 10660,9270 10700,9310 10700,9520 U2.10 10660,9760 10600,9820 10600,9940 10554,9986 10554,10300 ; P3.12 10554,10300 ; P1.90 10700.98,8180.98 10740,8220 10740,8260 10760,8280 11040,8280 ; 10870,8420 10901,8420 ; P1.83@11040,8055.98 P1.83@11040,8060 ; P1.83 11050.98,8060 P1.83@11040,8060 ; P3.24 v1(11200,10410) ; P3.26 11300,10440 11367,10507 v1(11367,10627) ; P1.69 11760,8065 11760,8180 11780,8200 11780,8240 11720,8300 ; v1(11960,8360) 11780,8360 11720,8300 ; 10901,8420 10979,8420 11069.5,8329.5 ; P1.83@11040,8060 11040,8300 11069.5,8329.5 ; 11069.5,8329.5 11380,8640 11440,8580 11440,8300 11720,8300
  BottomLayer w20: P1.113 9550.98,8229.02 ; P1.112@9600,8060 v1(9600,8220) ; P1.107 v1@9850.98,8319.02
  other v1: 9980,8390 10680,8430 9070,8480 11720,8530 12010,8540 9300,8580 9660,8580 9820,8680 10230,8680 12010,8740 10990,8760 11680,8810 10100,8870 9730,8910 9620,8990 9160,9190 11710,9260 11460,9700 11980,9940 10240,10120 9950,10270 9040,10300 10340,10500 9910,10690
HIT: J5.2 U3.15 | length 573.1
  TopLayer w8: U3.15 10340,9340 J5.2
IDSEL: P1.99 U1.75 | length 1009.3
  TopLayer w10: v1(10260.98,8255.98) 10460.98,8455.98 10501.55,8455.98 10818.55,8772.98 U1.75
  BottomLayer w10: P1.99 10250.98,8217.98 10260.98,8227.98 v1(10260.98,8255.98)
INT#: J1.1 P3.4 U1.59 | length 2609.3
  TopLayer w8: v1(10200,10400) 10220,10420 10960,10420 v1(10990,10390) ; U1.59@11100,9180 11102,9180 U1.59 11103.98,9223.98 11140,9260 11170,9260 11180,9270 11180,9400 11140,9440 10920,9440 10880,9480 10880,9520 11040,9680 v1(11100,9680)
  BottomLayer w8: P3.4 v1(10200,10400) ; v1(10990,10390) 11010,10390 11050,10350 11050,10050 11100,10000 J1.1 v1(11100,9680)
INTA: P1.119 U1.11 | length 2379.2
  TopLayer w8: v1(9520,8340) v1(9670,8340) ; v1(10950,8610) 10980,8580 11240,8580 11260,8560 11260,8520 11260.98,8520 U1.11
  BottomLayer w8: P1.119@9260,8065 9260,8220 9380,8340 v1(9520,8340) ; v1(9670,8340) 9700,8340 9970,8610 v1(10950,8610)
IOR#: P2.14 P3.5 U1.40 | length 3495.1
  TopLayer w8: v1(10260,10700) 10280,10700 10320,10740 P2.14 ; P3.5 10300,10120 10340,10080 10550,10080 10570,10100 10570,10153 10553,10170 10553,10228 10575,10250 10620,10250 10650,10280 10650,10325 10685,10360 10805,10360 10850,10315 10850,10150 10900,10100 v1(10940,10100) ; v1(11546,9060) 11580,9094 11720,9094 11726.02,9087.98 U1.40
  BottomLayer w8: v1(10260,10700) 10260,10640 10150,10530 10150,10445 10150,10280 10180,10250 10227,10250 10247,10230 10270,10230 P3.5 ; v1(10940,10100) 10940,9860 11040,9760 11040,9690 11320,9410 11320,9286 v1(11546,9060)
IOW#: P2.13 P3.7 U1.41 U4.11 | length 3974.9
  TopLayer w8: U4.11 10220,10720 P2.13 ; 10158.14,10658.14 10226.29,10590 v1(10270,10590) ; v1(10290,9210) 10300,9220 10850,9220 10888.5,9181.5 10888.5,9141.5 11160,8870 11250,8870 11310,8930 11390,8930 11410,8950 11410,9000 11520,9110 11520,9112 11640,9112 11670.98,9142.98 U1.41
  BottomLayer w8: v1(10270,10590) 10250,10570 10250,10275 10270,10255 10345,10255 P3.7 10390,10190 10390,9970 10310,9890 10310,9740 10410,9640 10410,9330 v1(10290,9210)
IRDY: P1.35 U1.8 | length 771.1
  TopLayer w10: P1.35 10700.98,8175.98 10780.98,8255.98 10973.98,8255.98 11166.98,8448.98 U1.8
MEMR#: P2.12 P3.9 U1.62 U2.11 | length 2645.3
  TopLayer w8: v1(10060,10370) 10128,10370 10150,10348 10340,10348 10350,10338 10350,10280 10380,10250 10450,10250 P3.9 ; v1(10060,10660) 10120,10720 P2.12 ; v1(10520,9800) 10520,9880 10540,9900 10650,9900 10660,9890 U2.11 ; v1(10650,9490) 10670,9490 10760,9400 10940,9400 10960,9380 10960,9270 11008.98,9221.02 U1.62 U1.62@11007,9180
  BottomLayer w8: v1@10060,10360 v1(10060,10660) ; P3.9 10470,10170 10470,9940 10510,9900 10510,9810 10610,9710 10610,9530 v1(10650,9490)
MEMW#: J5.1 P2.11 P3.11 U1.63 | length 2734.2
  TopLayer w8: P2.11 10020,10600 9900,10480 9900,10420 9920,10400 9960,10400 10100,10540 10450,10540 10530,10460 v1(10645,10460) ; J5.1 10900,9300 10980,9220 10980,9180 10977.98,9180 U1.63
  BottomLayer w8: v1(10645,10460) 10645,10272 10600,10227 10600,9990 10620,9970 10620,9840 10680,9780 10680,9600 10900,9380 J5.1
NetJ1_2: J1.2 P2.23 | length 969.7
  TopLayer w8: v1(11160,10680) 11220,10740 P2.23
  BottomLayer w8: v1(11160,10680) 11160,10440 11150,10430 11150,10125 11200,10075 J1.2
NetL10_A: L10.A R3.2 | length 100
  BottomLayer w8: R3.2 L10.A
NetL11_A: L11.A R3.3 | length 100
  BottomLayer w8: R3.3 L11.A
NetL12_A: L12.A R3.4 | length 100
  BottomLayer w8: R3.4 L12.A
NetL13_A: L13.A R3.5 | length 100
  BottomLayer w8: R3.5 L13.A
NetR1_2: J2.2 R1.2 U2.1 | length 2406.1
  TopLayer w8: U2.1 9840,9640 10520,9640 10620,9740 10800,9740 11060,10000 11630,10000 11760,9870 R1.2
  BottomLayer w8: J2.2 U2.1
NetR1_3: L1.A R1.3 R1.4 R1.5 | length 300
  TopLayer w8: R1.5 R1.4 R1.3 L1.A
NetR2_2: J3.8 R2.2 | length 261.4
  BottomLayer w8: R2.2 9180,9620 J3.8
NetR2_3: J3.6 R2.3 | length 261.4
  BottomLayer w8: R2.3 9180,9520 J3.6
NetR2_4: J3.4 R2.4 | length 261.4
  TopLayer w8: R2.4 9180,9420 J3.4
NetR2_5: J3.2 R2.5 | length 261.4
  TopLayer w8: R2.5 9180,9320 J3.2
NetU4_2: L10.K U4.2 | length 136.6
  TopLayer w8: U4.2 9180,10100 L10.K
NetU4_5: L11.K U4.5 | length 341.4
  BottomLayer w8: L11.K 9290,10030 9290,10170 9320,10200 9380,10200 U4.5
NetU4_6: L12.K U4.6 | length 227.3
  TopLayer w8: L12.K 9380,10050 9420,10090 9490,10090 U4.6
NetU4_9: L13.K U4.9 | length 409.7
  TopLayer w8: L13.K 9720,10020 U4.9
PAR: P1.82 U1.12 | length 609
  TopLayer w10: v1(11084,8221) 11084,8268 11100.27,8284.27 11100.98,8284.27 11192.7,8375.98 11260.98,8375.98 11292.98,8407.98 U1.12
  BottomLayer w10: v1(11084,8221) 11084,8215.02 11100.98,8215.02 P1.82
RESET: P2.2 U3.16 | length 2576.8
  TopLayer w8: P2.2 9120,10730 9190,10660 9440,10660 v1(9460,10680) ; v1(9690,9410) 9760,9480 10100,9480 U3.16
  BottomLayer w8: v1(9460,10680) 9590,10550 9590,10330 9490,10230 9490,10100 9530,10060 9530,9790 9480,9740 9480,9460 9540,9400 9680,9400 v1@9700,9420
RST#: P1.110 P3.3 U1.64 U3.17 U4.1 | length 4721.5
  TopLayer w8: U4.1 9090,10190 9340,10190 9400,10250 9910,10250 10020,10140 10140,10140 P3.3 ; U3.17 10060,9410 10190,9280 10880,9280 10945.98,9214.02 U1.64@10945.98,9180
  BottomLayer w8: P1.110 9700.98,8210 9600,8310.98 9600,8710 9910,9020 9910,9270 U3.17 10060,9450 10110,9500 10110,10090 10200,10180 P3.3
S0: J4.2 R2.9 U3.1 | length 971.1
  TopLayer w8: R2.9 J4.2 9360,8760 9460,8760 9527.07,8827.07 9527.07,9027.07 9580,9080 9720,9080 U3.1
S1: J4.4 R2.8 U3.11 | length 2169.8
  TopLayer w8: R2.8 J4.4 9350,8870 9440,8870 9460,8890 9460,9100 9520,9160 9670,9160 9840,9330 9960,9330 10010,9380 10010,9450 10020,9460 10090,9460 10111.27,9438.73 10111.27,9394.18 10135.46,9370 10190,9370 10210,9390 10210,9450 10230,9470 10590,9470 10640,9420 U3.11
S2: J4.6 R2.7 U3.18 | length 1098.4
  TopLayer w8: R2.7 J4.6 9350,9070 9350,9160 9370,9180 9660,9180 9840,9360 9900,9360 U3.18
S3: J4.8 R2.6 U3.19 | length 945.7
  TopLayer w8: R2.6 J4.8
  BottomLayer w8: J4.8 9350,9070 9510,9070 U3.19
TRDY: P1.89 U1.9 | length 765.6
  TopLayer w10: v1(10800.98,8215.98) 10969,8215.98 11169,8415.98 11180.98,8415.98 11197.98,8432.98 U1.9
  BottomLayer w10: P1.89@10750.98,8045.98 10750.98,8165.98 v1(10800.98,8215.98)
VCC: C1.1 C2.1 C3.1 C4.1 C5.1 C6.1 J4.1 J4.3 J4.5 J4.7 P1.5 P1.6 P1.61 P1.62 P1.63 P1.64 P1.117 P1.120 P2.3 P2.29 P2.48 P2.50 P2.51 P3.1 P3.2 R1.1 R3.1 U1.20 U1.61 U1.80 U2.20 U3.20 U4.20 | length 19176.5
  TopLayer w10: 10910,9210 10910,9150 10940,9120 11030,9120
  TopLayer w12: 10786,8550 U1.80@10856,8620 ; C4.1 v1(11040,9244) 11040.98,9243.02 U1.61 ; C3.1 11520,8440 11544.98,8464.98 U1.20 11544.98,8555.02 ; U1.20@11543,8525.96 11543,8560 ; 11544.98,8555.02 11540,8560 11544.98,8555.02
  TopLayer w15: R3.1 9140,9760 9500,9760 9540,9800 C6.1 9700,9800 U2.20 ; v1(9220,10700) P2.3 ; J4.1 9450,8820 9500,8870 9500,9070 9560,9130 9690,9130 9810,9250 10870,9250 10910,9210 ; v1(10220,10660) v1(10420,10660) 10480,10720 11040,10720 11118.5,10641.5 11191.5,10641.5 11274.36,10724.36 11835.64,10724.36 ; C2.1 10780,8550 10786,8550 ; U1.80 10895.98,8615.98 10930,8650 10980,8650 11010,8620 11280,8620 11300,8600 11500,8600 ; 11030,9120 11040.98,9130.98 U1.61 ; v1(11520,8610) 11510,8600 11503,8600 11543,8560 ; P2.29 11820,10740 11840,10720 11950,10720 11990,10680 v1(11990,10617) ; P1.61 12000.98,8440.98 12050.96,8490.96
  TopLayer w20: P1.5 9200.98,8220.98 9260,8280 ; P1.6@9260,8060 9260,8280 ; v1(9400,8280) C1.1 9260,8280 ; J4.3 J4.5 J4.7 ; v1(9520,9320) C5.1@9620,9320 ; P1.62 12050.96,8490.96
  BottomLayer w15: U4.20 9090,10390 9090,10380 ; R3.1 9080,10100 9090,10110 9090,10380 ; P1.120@9200,8060 9200,8220 C1.1 ; v1(9220,10700) 9290,10630 9290,10403 9267,10380 9090,10380 ; U3.20 9810,9470 9810,9760 ; U2.20 9760,9760 9810,9760 ; P2.51 P2.50 v1(10220,10660) 10100,10540 P3.2 P3.1 10010,10110 10010,9800 9970,9760 9810,9760 ; v1(10420,10660) 10420,10720 P2.48 ; v1(11040,9244) 11040,9100 11120,9020 11460,9020 11520,8960 11520,8440 ; R1.1 11860,8860 11920,8800 12068.48,8800 ; v1(11990,10617) 12067,10540 12067,9120 12067,8467 v1(12040,8440) v1@12050.98,8429.02 ; 12000,8440 12000.98,8439.02 ; P1.64 12000.98,8439.02 ; 12067,8510 12000.98,8443.98 12000.98,8439.02
  BottomLayer w20: P1.117 9350.98,8230.98 v1(9400,8280) ; C1.1 J4.1 J4.3 ; J4.7 9400,9200 v1(9520,9320) 9660,9320 U3.20 ; 11520,8440 v1(12040,8440) ; P1.63 v1@12050.98,8429.02
  other v1: 12050.96,8240
pads on no net: P1.2 P1.4 P1.7 P1.8 P1.10 P1.14 P1.17 P1.18 P1.19 P1.22 P1.25 P1.28 P1.31 P1.34 P1.36 P1.38 P1.39 P1.40 P1.41 P1.42 P1.43 P1.46 P1.49 P1.54 P1.57 P1.59 P1.60 P1.65 P1.66 P1.72 P1.77 P1.80 P1.84 P1.85 P1.86 P1.87 P1.88 P1.92 P1.95 P1.98 P1.101 P1.104 P1.106 P1.108 P1.109 P1.111 P1.114 P1.115 P1.116 P1.118 P1.121 P1.122 P1.124 P2.4 P2.5 P2.6 P2.8 P2.15 P2.16 P2.17 P2.18 P2.19 P2.20 P2.21 P2.22 P2.24 P2.25 P2.26 P2.27 P2.28 P2.30 P2.53 P2.62 U3.13 U3.14 U4.12 U4.15 U4.16 U4.19

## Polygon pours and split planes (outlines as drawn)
GND on TopLayer "TopLayer-GND 1" (hatched 90Degree grid 20 track 20, remove dead copper, pour order 1): 8960,8200 12090,8200 12090,10710 8960,10710
GND on BottomLayer "BottomLayer-GND" (hatched 90Degree grid 20 track 20, remove dead copper, pour order 2): 8960,8200 12090,8200 12090,10710 8960,10710

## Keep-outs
KeepOutLayer:
  circle w10: c11980,10050 r50
  circle w10: c9125.98,8320.98 r50
  lines w10: 8960.98,8195.98 8960.98,10900 12090.98,10900 12090.98,8195.98

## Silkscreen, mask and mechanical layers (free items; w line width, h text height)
TopOverlay:
  drawing of 2669 lines, arcs and shapes, not listed
  text "GND" at 9080,10620 h40 r90
  text "+5V" at 11820,10620 h40 r90
  text "GND" at 12060,10620 h40 r90
  text "-12V" at 9640,10590 h40 r90
  text "+12V" at 9840,10590 h40 r90
  text "+5V" at 9250,10560 h40 r90
  text "GND" at 11220,10440 h40 r90
  text "INT#" at 10220,10430 h40 r90
  text "A13" at 11910,10410 h40 r90
  text "+5V" at 10120,10380 h40 r90
  text "GND" at 10310,10380 h40 r90
  text "GND" at 10420,10380 h40 r90
  text "GND" at 10520,10380 h40 r90
  text "GND" at 10610,10380 h40 r90
  text "D1" at 10720,10380 h40 r90
  text "D3" at 10820,10380 h40 r90
  text "D4" at 10920,10380 h40 r90
  text "D6" at 11050,10380 h40 r90
  text "A3" at 11450,10380 h40 r90
  text "A5" at 11520,10380 h40 r90
  text "A7" at 11620,10380 h40 r90
  text "A9" at 11720,10380 h40 r90
  text "A11" at 11830,10380 h40 r90
  text "GND" at 11120,10370 h40 r90
  text "GND" at 11320,10370 h40 r90
  text "A15" at 12070,10370 h40 r90
  text "D0" at 10720,10060 h40 r90
  text "D5" at 11020,10060 h40 r90
  text "D7" at 11120,10060 h40 r90
  text "A0" at 11220,10060 h40 r90
  text "A1" at 11310,10060 h40 r90
  text "A14" at 12070,10060 h30 r90
  text "A2" at 11420,10050 h40 r90
  text "A4" at 11520,10050 h40 r90
  text "A6" at 11620,10050 h40 r90
  text "A8" at 11720,10050 h40 r90
  text "+5V" at 10120,10020 h40 r90
  text "D2" at 10820,10020 h40 r90
  text "A10" at 11820,10020 h40 r90
  text "A12" at 11910,10020 h40 r90
  text "RST#" at 10211.33,9991.33 h40 r90
  text "IOR#" at 10320,9990 h40 r90
  text "IOW#" at 10420,9990 h40 r90
  text "GND" at 10930,9970 h40 r90
  text "MEMW#" at 10620,9950 h40 r90
  text "MEMR#" at 10510,9930 h40 r90
  text "INT#" at 11060,9760 h50
  text "D4" at 9150,9580 h50
  text "IOP-HIT" at 10760,9510 h50
  text "D3" at 9150,9490 h50
  text "PCI-ID" at 9840,9470 h50
  text "D2" at 9149.24,9389.24 h50
  text "D1" at 9153.57,9293.57 h50
  text "CH365  DEMO" at 11964,9120 h50 r90
  text "S3" at 9150,9096 h50
  text "S2" at 9150,8996 h50
  text "www.winchiphead.com" at 12050,8940 h50 r90
  text "S1" at 9150,8896 h50
  text "S0" at 9150,8796 h50
  text "CLK" at 10568,8757 h50
  text "ADDR-SEL" at 9190,8620 h40
  text "http://wch.cn" at 9834.68,8423.97 h50
TopSolder:
  rectangle: 8960,7900 12090,8180
BottomSolder:
  rectangle: 8960,7900 12090,8180
Mechanical 1:
  circle w10: c9125.98,8320.98 r50
  circle w10: c11980,10050 r50
  lines w10: 8960.98,7920.98 8960.98,8175.98 8960.98,10900 12090.98,10900 12090.98,8195.98 12090.98,7920.98 12065.98,7895.98 11535.98,7895.98 11515.98,7915.98 11515.98,8170.98 ccw(c11475.98,8170.98) 11435.98,8170.98 11435.98,7915.98 11415.98,7895.98 8985.98,7895.98 8960.98,7920.98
